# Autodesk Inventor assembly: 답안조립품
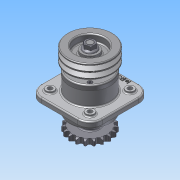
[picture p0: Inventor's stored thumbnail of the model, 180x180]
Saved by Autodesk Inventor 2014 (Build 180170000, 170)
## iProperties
Created: 2015-09
Part Number: 답안조립품
Document SubType Name: Assembly
Designer: study
Author: study
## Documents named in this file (11)
- C:\Users\study\Desktop\450909V1006\답안조립품.iam
- C:\Users\study\Desktop\450909V1006\1-본체.ipt
- C:\Users\study\Desktop\450909V1006\2-커버.ipt
- C:\Users\study\Desktop\450909V1006\6-베어링 6206.ipt
- C:\Users\study\Desktop\450909V1006\8-오일실 30x42.ipt
- C:\Users\study\Desktop\450909V1006\10-M6.ipt
- C:\Users\study\Desktop\450909V1006\3-축.ipt
- C:\Users\study\Desktop\450909V1006\5-체인 스프로킷.ipt
- C:\Users\study\Desktop\450909V1006\9-M16-너트.ipt
- C:\Users\study\Desktop\450909V1006\11-키 6x6.ipt
- C:\Users\study\Desktop\450909V1006\4-V벨트풀리.ipt
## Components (22 placed, 10 different names)
1. 1-본체:1
2. 2-커버:1
3. 6-베어링 6206:1
4. 8-8-오일실 30x42:1
5. 3-축:1 — 각도:1, 각도:3
6. 2-커버:2
7. 6-베어링 6206:2
8. 8-8-오일실 30x42:2
9. 5-체인 스프로킷:1 — 각도:2
10. 9-M16 너트:1
11. 11-키 6x6:1 — 각도:1, 각도:2
12. 4-V벨트풀리:1 — 각도:4
13. 9-M16 너트:2
14. 11-키 6x6:2 — 각도:3, 각도:4
15. 10-M6:1
16. 10-M6:2
17. 10-M6:3
18. 10-M6:4
19. 10-M6:5
20. 10-M6:6
21. 10-M6:7
22. 10-M6:8
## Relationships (4: Angle 4)
- 각도:1 [Angle]: 3-축:1 ↔ 11-키 6x6:1
- 각도:2 [Angle]: 5-체인 스프로킷:1 ↔ 11-키 6x6:1
- 각도:3 [Angle]: 3-축:1 ↔ 11-키 6x6:2
- 각도:4 [Angle]: 4-V벨트풀리:1 ↔ 11-키 6x6:2
